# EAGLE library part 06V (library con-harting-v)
CONNECTOR
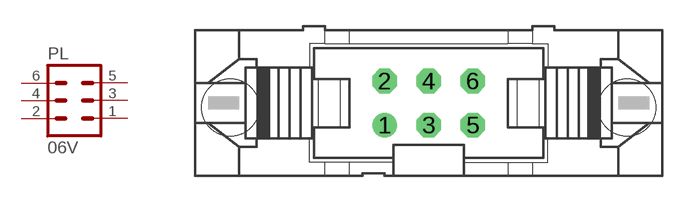
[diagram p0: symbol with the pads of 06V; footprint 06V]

Designator prefix PL

## 06V (OC_FARNELL: unknown; OC_NEWARK: unknown)  [06V]
1  1  pas
2  2  pas
3  3  pas
4  4  pas
5  5  pas
6  6  pas

## Footprint 06V (pad centres in mm)
CONNECTOR
drill 0.914 round: 1 -2.54,-1.27
drill 0.914 octagon: 2 -2.54,1.27; 3 0,-1.27; 4 0,1.27; 5 2.54,-1.27; 6 2.54,1.27
hole 3.302 at 11.43,-0.254
hole 3.302 at -11.43,-0.254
